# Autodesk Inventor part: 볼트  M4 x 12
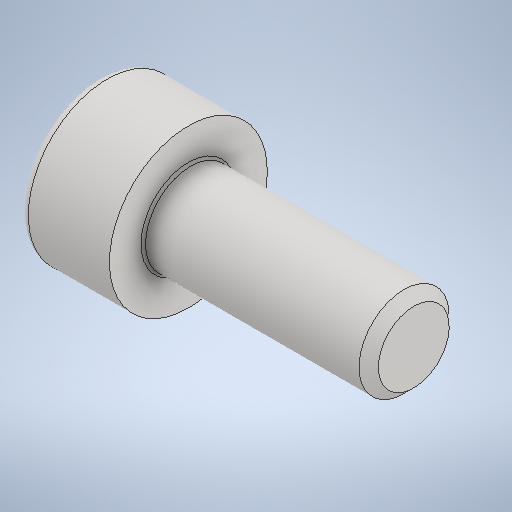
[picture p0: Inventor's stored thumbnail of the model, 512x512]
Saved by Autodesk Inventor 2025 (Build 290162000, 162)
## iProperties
Created: 2024-08
Part Number: 볼트  M4 x 12
Material: 스테인리스강
Description: 6각머리 태핑 나사
Document SubType Name: Modeling
Designer: 학생
Density: 8.08 g/cm^3
Appearance: 기본값
Author: jhkim
Sending System: Autodesk Inventor 2025
Preprocessor: ST-DEVELOPER v20
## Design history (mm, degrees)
feature "Solid1"
node "솔리드1"
